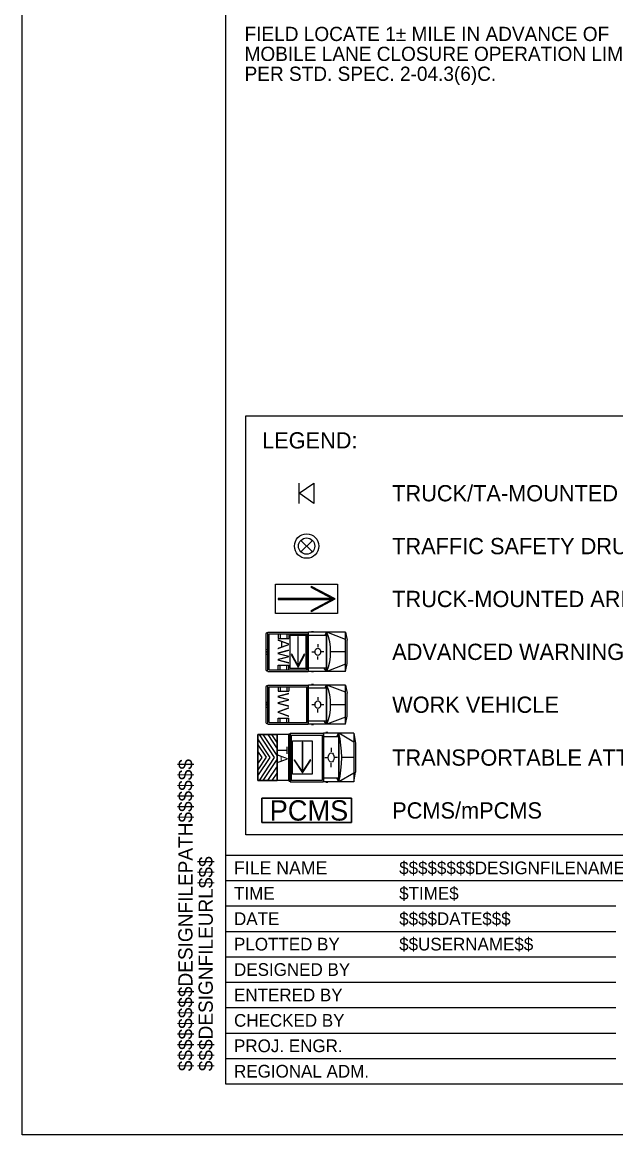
# Model space of a CAD drawing. Extents: x 0 to 17, y 0 to 11.
# Drawn here: x 0 to 2.92, y 0 to 5.47 of the extents above; entities that cross this region are included whole.
import ezdxf

# ---------------------------------------------------------------- set-up
doc = ezdxf.new("R2010")
doc.units = 0
for name, color, linetype in [('SH_GI_PlotLimits', 7, 'Continuous'), ('SH_GI_SheetBorder1', 7, 'Continuous'), ('SH_GI_SheetBorder3', 7, 'Continuous'), ('SH_GI_SheetTextInCells', 7, 'Continuous'), ('SH_GI_TitleBlockText', 7, 'Continuous'), ('TR_WZ_PCMS', 7, 'Continuous'), ('TR_WZ_PortableChangeMessageSign', 7, 'Continuous'), ('TR_WZ_PortableSignMountBlk-Org', 7, 'Continuous'), ('TR_WZ_ProtectiveVehicle', 7, 'Continuous'), ('TR_WZ_TrafficSafetyDrum', 7, 'Continuous'), ('TR_WZ_TransportableAttenuator', 7, 'Continuous'), ('TR_WZ_WorkZoneTextCurrent', 7, 'Continuous')]:
    doc.layers.add(name, color=color, linetype=linetype)

msp = doc.modelspace()

# ---------------------------------------------------------------- linework, layer by layer
at = {"layer": 'SH_GI_PlotLimits'}
msp.add_lwpolyline([(0, 11), (17, 11), (17, 0), (0, 0)], close=True, dxfattribs=at)
at = {"layer": 'SH_GI_SheetBorder1'}
for p, q in [((1, 1.125), (2.92, 1.125)), ((1, 1), (2.92, 1)), ((1, 0.875), (2.92, 0.875)), ((1, 0.75), (2.92, 0.75)), ((1, 0.625), (2.92, 0.625)), ((1, 0.5), (2.92, 0.5)), ((1, 0.375), (2.92, 0.375))]:
    msp.add_line(p, q, dxfattribs=at)
at = {"layer": 'SH_GI_SheetBorder3'}
for p, q in [((1, 10.75), (1, 0.25)), ((1, 1.375), (16.75, 1.375)), ((1, 1.25), (6.52, 1.25)), ((1, 0.25), (16.75, 0.25))]:
    msp.add_line(p, q, dxfattribs=at)
at = {"layer": 'TR_WZ_PCMS'}
for points in [[(1.6191, 1.655), (1.6191, 1.535), (1.1791, 1.535), (1.1791, 1.655), (1.6191, 1.655)], [(1.1791, 1.655), (1.1791, 1.535), (1.6191, 1.535), (1.6191, 1.655), (1.1791, 1.655)]]:
    msp.add_lwpolyline(points, dxfattribs=at)
at = {"layer": 'TR_WZ_PortableSignMountBlk-Org'}
msp.add_line((1.3631, 3.105), (1.3631, 3.205), dxfattribs=at)
msp.add_lwpolyline([(1.3631, 3.155), (1.435, 3.205), (1.435, 3.105)], close=True, dxfattribs=at)
at = {"layer": 'TR_WZ_ProtectiveVehicle'}
for p, q in [((1.2035, 2.4678), (1.2078, 2.4678)), ((1.2078, 2.2822), (1.2078, 2.4678)), ((1.2085, 2.471), (1.406, 2.471)), ((1.2085, 2.279), (1.2085, 2.471)), ((1.2141, 2.2867), (1.2141, 2.4633)), ((1.2141, 2.4633), (1.4004, 2.4633)), ((1.2586, 2.4633), (1.2586, 2.4413)), ((1.2692, 2.4633), (1.2692, 2.4413)), ((1.3018, 2.4633), (1.3018, 2.4413)), ((1.3114, 2.4633), (1.3114, 2.4413)), ((1.4004, 2.2867), (1.4004, 2.4633)), ((1.406, 2.279), (1.406, 2.471)), ((1.4086, 2.279), (1.4086, 2.471)), ((1.59, 2.471), (1.4086, 2.471)), ((1.4334, 2.4737), (1.4225, 2.4737)), ((1.4881, 2.4561), (1.4976, 2.471)), ((1.4976, 2.279), (1.4976, 2.471)), ((1.4993, 2.279), (1.4993, 2.471)), ((1.59, 2.4358), (1.4993, 2.471)), ((1.59, 2.279), (1.59, 2.471)), ((1.59, 2.471), (1.5989, 2.4322)), ((1.1993, 2.288), (1.1993, 2.462)), ((1.2586, 2.4413), (1.3114, 2.4413)), ((1.4976, 2.4561), (1.4086, 2.4561)), ((1.4535, 2.4119), (1.4537, 2.3975)), ((1.5989, 2.3178), (1.5989, 2.4322)), ((1.1993, 2.3885), (1.2078, 2.3849)), ((1.1993, 2.3615), (1.2078, 2.3651)), ((1.2016, 2.375), (1.2055, 2.375)), ((1.2035, 2.3723), (1.2035, 2.3777)), ((1.4245, 2.3757), (1.4388, 2.3754)), ((1.4406, 2.3753), (1.4406, 2.3753)), ((1.4831, 2.3749), (1.471, 2.3749)), ((1.59, 2.375), (1.5171, 2.375)), ((1.2586, 2.3087), (1.3114, 2.3087)), ((1.2586, 2.2867), (1.2586, 2.3087)), ((1.2692, 2.2867), (1.2692, 2.3087)), ((1.3018, 2.2867), (1.3018, 2.3087)), ((1.3114, 2.2867), (1.3114, 2.3087)), ((1.4541, 2.3369), (1.4541, 2.3525)), ((1.59, 2.3142), (1.4993, 2.279)), ((1.59, 2.279), (1.5989, 2.3178)), ((1.2035, 2.2822), (1.2078, 2.2822)), ((1.2085, 2.279), (1.406, 2.279)), ((1.2141, 2.2867), (1.4004, 2.2867)), ((1.4976, 2.2939), (1.4086, 2.2939)), ((1.59, 2.279), (1.4086, 2.279)), ((1.4334, 2.2763), (1.4225, 2.2763)), ((1.4976, 2.279), (1.4861, 2.2939)), ((1.1993, 2.028), (1.1993, 2.202)), ((1.2035, 2.2078), (1.2078, 2.2078)), ((1.2078, 2.0222), (1.2078, 2.2078)), ((1.2085, 2.211), (1.406, 2.211)), ((1.2085, 2.019), (1.2085, 2.211)), ((1.2141, 2.0267), (1.2141, 2.2033)), ((1.2141, 2.2033), (1.4004, 2.2033)), ((1.2586, 2.2033), (1.2586, 2.1813)), ((1.2692, 2.2033), (1.2692, 2.1813)), ((1.3018, 2.2033), (1.3018, 2.1813)), ((1.3114, 2.2033), (1.3114, 2.1813)), ((1.4004, 2.0267), (1.4004, 2.2033)), ((1.406, 2.019), (1.406, 2.211)), ((1.4086, 2.019), (1.4086, 2.211)), ((1.59, 2.211), (1.4086, 2.211)), ((1.4976, 2.1961), (1.4086, 2.1961)), ((1.4334, 2.2137), (1.4225, 2.2137)), ((1.4881, 2.1961), (1.4976, 2.211)), ((1.4976, 2.019), (1.4976, 2.211)), ((1.4993, 2.019), (1.4993, 2.211)), ((1.59, 2.1758), (1.4993, 2.211)), ((1.59, 2.019), (1.59, 2.211)), ((1.59, 2.211), (1.5989, 2.1722)), ((1.2586, 2.1813), (1.3114, 2.1813)), ((1.4535, 2.1519), (1.4537, 2.1375)), ((1.5989, 2.0578), (1.5989, 2.1722)), ((1.1993, 2.1285), (1.2078, 2.1249)), ((1.1993, 2.1015), (1.2078, 2.1051)), ((1.2016, 2.115), (1.2055, 2.115)), ((1.2035, 2.1123), (1.2035, 2.1177)), ((1.4245, 2.1157), (1.4388, 2.1154)), ((1.4406, 2.1153), (1.4406, 2.1153)), ((1.4541, 2.0769), (1.4541, 2.0925)), ((1.4831, 2.1149), (1.471, 2.1149)), ((1.59, 2.115), (1.5171, 2.115)), ((1.2141, 2.0267), (1.4004, 2.0267)), ((1.2586, 2.0487), (1.3114, 2.0487)), ((1.2586, 2.0267), (1.2586, 2.0487)), ((1.2692, 2.0267), (1.2692, 2.0487)), ((1.3018, 2.0267), (1.3018, 2.0487)), ((1.3114, 2.0267), (1.3114, 2.0487)), ((1.4976, 2.0339), (1.4086, 2.0339)), ((1.4976, 2.019), (1.4861, 2.0339)), ((1.59, 2.0542), (1.4993, 2.019)), ((1.59, 2.019), (1.5989, 2.0578)), ((1.2035, 2.0222), (1.2078, 2.0222)), ((1.2085, 2.019), (1.406, 2.019)), ((1.59, 2.019), (1.4086, 2.019)), ((1.4334, 2.0163), (1.4225, 2.0163))]:
    msp.add_line(p, q, dxfattribs=at)
for centre, major_axis, start_param, end_param in [((1.2035, 2.462), (0, 0.00586), 0, 1.570796), ((1.3697, 2.375), (0, 0.2015), 4.215667, 5.208926), ((1.2035, 2.288), (0, -0.00586), 4.712389, 6.283185), ((1.2035, 2.202), (0, 0.00586), 0, 1.570796), ((1.3697, 2.115), (0, 0.2015), 4.215667, 5.208926), ((1.2035, 2.028), (0, -0.00586), 4.712389, 6.283185)]:
    msp.add_ellipse(centre, major_axis=major_axis, ratio=0.73155, start_param=start_param, end_param=end_param, dxfattribs=at)
for centre, major_axis in [((1.2035, 2.375), (0, -0.0027)), ((1.4541, 2.375), (0, -0.0185)), ((1.2035, 2.115), (0, -0.0027)), ((1.4541, 2.115), (0, -0.0185))]:
    msp.add_ellipse(centre, major_axis=major_axis, ratio=0.73155, dxfattribs=at)
at = {"layer": 'TR_WZ_TrafficSafetyDrum'}
for p, q in [((1.3708, 2.9233), (1.4273, 2.8667)), ((1.4273, 2.9233), (1.3708, 2.8667))]:
    msp.add_line(p, q, dxfattribs=at)
for radius in [0.06, 0.06, 0.04]:
    msp.add_circle((1.3991, 2.895), radius, dxfattribs=at)
at = {"layer": 'TR_WZ_TransportableAttenuator'}
for p, q in [((1.3137, 1.9711), (1.3173, 1.9711)), ((1.3173, 1.9711), (1.3173, 1.739)), ((1.3178, 1.975), (1.4803, 1.975)), ((1.3178, 1.975), (1.3178, 1.735)), ((1.4803, 1.975), (1.4803, 1.735)), ((1.4825, 1.975), (1.4825, 1.735)), ((1.6317, 1.975), (1.4825, 1.975)), ((1.5028, 1.9784), (1.4939, 1.9784)), ((1.5558, 1.975), (1.5463, 1.9564)), ((1.5558, 1.975), (1.5558, 1.735)), ((1.5571, 1.975), (1.5571, 1.735)), ((1.6317, 1.9311), (1.5571, 1.975)), ((1.6317, 1.975), (1.6317, 1.735)), ((1.6317, 1.975), (1.6391, 1.9266)), ((1.1591, 1.9173), (1.1591, 1.9465)), ((1.2192, 1.8559), (1.1591, 1.9465)), ((1.1591, 1.9465), (1.1591, 1.9173)), ((1.1591, 1.9173), (1.1999, 1.8562)), ((1.1653, 1.9679), (1.1857, 1.9679)), ((1.1653, 1.9679), (1.2401, 1.8552)), ((1.1857, 1.9679), (1.1653, 1.9679)), ((1.2534, 1.8652), (1.1857, 1.9679)), ((1.2078, 1.9679), (1.2281, 1.9679)), ((1.2281, 1.9679), (1.2078, 1.9679)), ((1.2078, 1.9679), (1.2534, 1.8984)), ((1.2534, 1.9298), (1.2281, 1.9679)), ((1.3178, 1.9679), (1.2534, 1.9679)), ((1.2534, 1.7426), (1.2534, 1.9679)), ((1.2534, 1.9298), (1.2534, 1.8984)), ((1.2534, 1.8984), (1.2534, 1.9298)), ((1.3102, 1.9638), (1.3102, 1.7463)), ((1.3178, 1.9675), (1.3178, 1.7426)), ((1.3224, 1.9655), (1.3224, 1.7446)), ((1.3224, 1.9655), (1.4757, 1.9655)), ((1.4757, 1.9655), (1.4757, 1.7446)), ((1.5558, 1.9564), (1.4825, 1.9564)), ((1.6391, 1.9266), (1.6391, 1.7835)), ((1.1591, 1.824), (1.1591, 1.8864)), ((1.1799, 1.8554), (1.1591, 1.8864)), ((1.1591, 1.8864), (1.1591, 1.824)), ((1.2534, 1.8652), (1.2534, 1.8451)), ((1.2534, 1.8451), (1.2534, 1.8652)), ((1.3102, 1.8719), (1.3173, 1.8674)), ((1.52, 1.9026), (1.5199, 1.8832)), ((1.1999, 1.8562), (1.1591, 1.7948)), ((1.1591, 1.7654), (1.2192, 1.8559)), ((1.1591, 1.824), (1.1799, 1.8554)), ((1.2401, 1.8552), (1.1652, 1.7425)), ((1.1853, 1.7425), (1.2534, 1.8451)), ((1.2534, 1.8119), (1.2073, 1.7425)), ((1.2534, 1.8119), (1.2534, 1.7788)), ((1.2534, 1.7788), (1.2534, 1.8119)), ((1.3102, 1.8381), (1.3173, 1.8426)), ((1.3121, 1.855), (1.3154, 1.855)), ((1.3137, 1.8584), (1.3137, 1.8516)), ((1.4882, 1.8552), (1.5015, 1.8551)), ((1.5051, 1.8546), (1.5051, 1.8546)), ((1.52, 1.8075), (1.5199, 1.8269)), ((1.5517, 1.8552), (1.5384, 1.8551)), ((1.6317, 1.855), (1.5718, 1.855)), ((1.1591, 1.7654), (1.1591, 1.7948)), ((1.1591, 1.7948), (1.1591, 1.7654)), ((1.2288, 1.7425), (1.2534, 1.7788)), ((1.5558, 1.7536), (1.4825, 1.7536)), ((1.5479, 1.7536), (1.5558, 1.735)), ((1.6317, 1.779), (1.5571, 1.735)), ((1.6317, 1.735), (1.6391, 1.7835)), ((1.1853, 1.7425), (1.1652, 1.7425)), ((1.1652, 1.7425), (1.1853, 1.7425)), ((1.2288, 1.7425), (1.2073, 1.7425)), ((1.2073, 1.7425), (1.2288, 1.7425)), ((1.3178, 1.7426), (1.2534, 1.7426)), ((1.3137, 1.739), (1.3173, 1.739)), ((1.3178, 1.735), (1.4803, 1.735)), ((1.3224, 1.7446), (1.4757, 1.7446)), ((1.6317, 1.735), (1.4825, 1.735)), ((1.5028, 1.7317), (1.4939, 1.7317))]:
    msp.add_line(p, q, dxfattribs=at)
for points in [[(1.2464, 2.563), (1.2464, 2.707), (1.5517, 2.707), (1.5517, 2.563)], [(1.5395, 2.635), (1.4232, 2.697), (1.4199, 2.693), (1.5241, 2.6374)], [(1.2587, 2.6326), (1.5241, 2.6326), (1.5241, 2.6374), (1.2587, 2.6374)], [(1.4232, 2.573), (1.5395, 2.635), (1.5241, 2.6326), (1.4199, 2.577)], [(1.5395, 2.635), (1.5241, 2.6374), (1.5241, 2.6326)], [(1.3183, 2.4564), (1.3951, 2.4564), (1.3951, 2.2936), (1.3183, 2.2936)], [(1.3554, 2.4499), (1.3554, 2.3083), (1.358, 2.3083), (1.358, 2.4499)], [(1.3236, 2.3621), (1.3567, 2.3001), (1.3554, 2.3083), (1.3257, 2.3639)], [(1.3567, 2.3001), (1.3897, 2.3621), (1.3876, 2.3639), (1.358, 2.3083)], [(1.3567, 2.3001), (1.358, 2.3083), (1.3554, 2.3083)], [(1.2534, 1.7425), (1.1591, 1.7425), (1.1591, 1.9679), (1.2534, 1.9679)], [(1.3304, 1.9365), (1.4264, 1.9365), (1.4264, 1.7736), (1.3304, 1.7736)], [(1.3768, 1.9299), (1.3768, 1.7883), (1.38, 1.7883), (1.38, 1.9299)], [(1.3371, 1.8422), (1.3784, 1.7802), (1.3768, 1.7883), (1.3397, 1.8439)], [(1.3784, 1.7802), (1.4197, 1.8422), (1.4171, 1.8439), (1.38, 1.7883)], [(1.3784, 1.7802), (1.38, 1.7883), (1.3768, 1.7883)]]:
    msp.add_lwpolyline(points, close=True, dxfattribs=at)
msp.add_lwpolyline([(1.2534, 1.9679), (1.1591, 1.9679), (1.1591, 1.7425), (1.2534, 1.7426)], dxfattribs=at)
for centre, major_axis, start_param, end_param in [((1.3137, 1.9638), (0, 0.00732), 6.283185, 7.853982), ((1.4505, 1.855), (0, 0.2519), 4.215852, 5.209111), ((1.3137, 1.7463), (0, -0.00732), 4.712389, 6.283185)]:
    msp.add_ellipse(centre, major_axis=major_axis, ratio=0.481608, start_param=start_param, end_param=end_param, dxfattribs=at)
for centre, major_axis, ratio in [((1.5199, 1.855), (0, -0.0231), 0.642144), ((1.5199, 1.855), (0, 0.0231), 0.642144), ((1.3137, 1.855), (0, -0.00338), 0.481608)]:
    msp.add_ellipse(centre, major_axis=major_axis, ratio=ratio, dxfattribs=at)
at = {"layer": 'TR_WZ_WorkZoneTextCurrent'}
msp.add_lwpolyline([(1.1, 3.535), (4.2886, 3.535), (4.2886, 1.475), (1.1, 1.475)], close=True, dxfattribs=at)

# ---------------------------------------------------------------- texts
at = {"layer": 'SH_GI_SheetTextInCells'}
for s, height, p in [('FILE NAME', 0.065, (1.042, 1.28)), ('TIME', 0.0625, (1.042, 1.1562)), ('DATE', 0.0625, (1.042, 1.0312)), ('PLOTTED BY', 0.0625, (1.042, 0.9062)), ('DESIGNED BY', 0.0625, (1.042, 0.7812)), ('ENTERED BY', 0.0625, (1.042, 0.6562)), ('CHECKED BY', 0.0625, (1.042, 0.5312)), ('PROJ. ENGR.', 0.0625, (1.042, 0.4062)), ('REGIONAL ADM.', 0.0625, (1.042, 0.2812))]:
    msp.add_text(s, height=height, dxfattribs=at).set_placement(p)
at = {"layer": 'SH_GI_TitleBlockText'}
for s, p in [('$$$$$$$$DESIGNFILEPATH$$$$$$', (0.8377, 0.3125)), ('$$$DESIGNFILEURL$$$', (0.9375, 0.3125))]:
    msp.add_text(s, height=0.07, rotation=90, dxfattribs=at).set_placement(p)
for s, p in [('$$$$$$$$DESIGNFILENAME$$$$$$', (1.8545, 1.2812)), ('$TIME$', (1.8545, 1.1562)), ('$$$$DATE$$$', (1.8545, 1.0312)), ('$$USERNAME$$', (1.8545, 0.9062))]:
    msp.add_text(s, height=0.0625, dxfattribs=at).set_placement(p)
at = {"layer": 'TR_WZ_PCMS'}
msp.add_text('PCMS', height=0.1, rotation=360, dxfattribs=at).set_placement((1.2173, 1.545))
at = {"layer": 'TR_WZ_PortableChangeMessageSign'}
for s, p in [('FIELD LOCATE 1± MILE IN ADVANCE OF ', (1.0938, 5.3789)), ('MOBILE LANE CLOSURE OPERATION LIMITS ', (1.0938, 5.2809)), ('PER STD. SPEC. 2-04.3(6)C.', (1.0938, 5.1829))]:
    msp.add_text(s, height=0.07, rotation=360, dxfattribs=at).set_placement(p)
at = {"layer": 'TR_WZ_ProtectiveVehicle'}
for s, p in [('AW', (1.257, 2.4371)), ('WV', (1.257, 2.1743))]:
    msp.add_text(s, height=0.056, rotation=270, dxfattribs=at).set_placement(p)
at = {"layer": 'TR_WZ_TransportableAttenuator'}
msp.add_text('TA', height=0.048, rotation=270, dxfattribs=at).set_placement((1.2572, 1.9097))
at = {"layer": 'TR_WZ_WorkZoneTextCurrent'}
for s, p in [('LEGEND:', (1.18, 3.375)), ('TRUCK/TA-MOUNTED SIGNS (SEE NOTE 2)', (1.82, 3.115)), ('TRAFFIC SAFETY DRUMS', (1.82, 2.855)), ('TRUCK-MOUNTED ARROW DISPLAY (SEE NOTE 2)', (1.82, 2.595)), ('ADVANCED WARNING VEHICLE', (1.82, 2.335)), ('WORK VEHICLE', (1.82, 2.075)), ('TRANSPORTABLE ATTENUATOR (TL-3)', (1.82, 1.815)), ('PCMS/mPCMS', (1.82, 1.555))]:
    msp.add_text(s, height=0.08, rotation=360, dxfattribs=at).set_placement(p)

doc.saveas('drawing.dxf')
